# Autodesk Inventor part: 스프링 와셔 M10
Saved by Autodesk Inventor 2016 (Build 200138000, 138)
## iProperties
Created: 2024-08
Part Number: 스프링 와셔 M10
Material: 일반
Description: 스프링 잠금 와셔
Document SubType Name: Modeling
Designer: pc-2
Density: 1 g/cm^3
Appearance: 기본값
Author: jhkim
Sending System: Autodesk Inventor 2025
Preprocessor: ST-DEVELOPER v20
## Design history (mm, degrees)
node "스프링 와셔 M101"
node "솔리드1"
body "Solid1"
